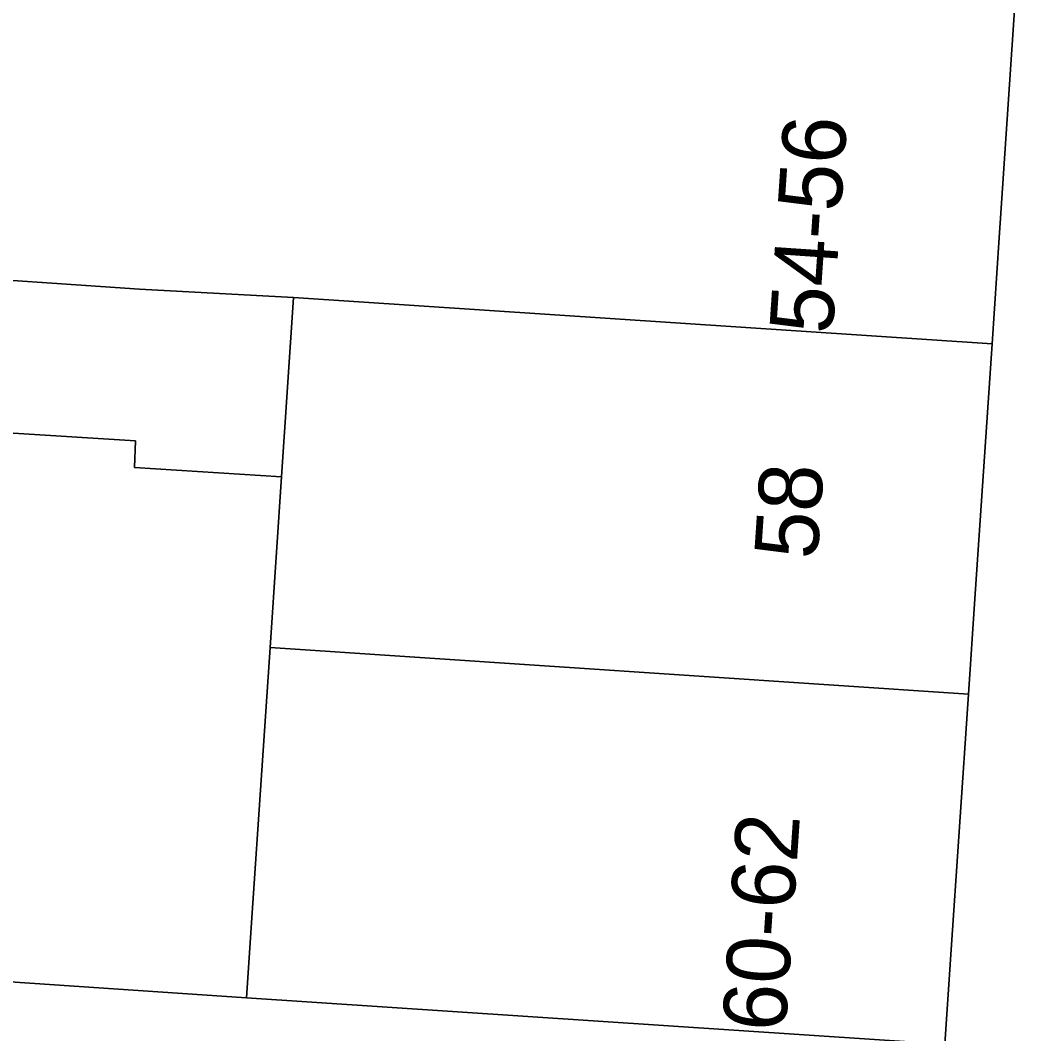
# Model space of a CAD drawing. Extents: x 159960 to 160866, y 382700 to 383354.
# Drawn here: x 160554.15 to 160570.09, y 382879.56 to 382895.53 of the extents above; entities that cross this region are included whole.
import ezdxf

# ---------------------------------------------------------------- set-up
doc = ezdxf.new("R2010")
doc.units = 0
for name, color, linetype in [('IMGEO_Erf', 7, 'Continuous'), ('IMGEO_Pand', 7, 'Continuous'), ('IMGEO_Pand_nummerreeks', 7, 'Continuous'), ('IMGEO_Voetpad_open', 7, 'Continuous')]:
    doc.layers.add(name, color=color, linetype=linetype)

msp = doc.modelspace()

# ---------------------------------------------------------------- linework, layer by layer
at = {"layer": 'IMGEO_Erf'}
msp.add_lwpolyline([(160558.093, 382885.645), (160558.195, 382887.149), (160558.275, 382888.339), (160555.958, 382888.484), (160555.97, 382888.904), (160550.348, 382889.255), (160550.318, 382887.835), (160545.028, 382888.202), (160545.001, 382887.778), (160544.75, 382881.002), (160557.721, 382880.127), (160557.811, 382881.464)], close=True, dxfattribs=at)
at = {"layer": 'IMGEO_Pand'}
for points in [[(160569.847, 382895.857), (160558.833, 382896.589), (160552.857, 382896.986), (160552.795, 382896.076), (160552.96, 382896.065), (160552.651, 382891.528), (160556.037, 382891.294), (160558.466, 382891.163), (160569.48, 382890.432), (160569.593, 382892.102)], [(160558.466, 382891.163), (160556.037, 382891.294), (160552.651, 382891.528), (160547.258, 382891.902), (160545.277, 382892.039), (160545.028, 382888.202), (160550.318, 382887.835), (160550.348, 382889.255), (160555.97, 382888.904), (160555.958, 382888.484), (160558.275, 382888.339)], [(160569.48, 382890.432), (160558.466, 382891.163), (160558.275, 382888.339), (160558.195, 382887.149), (160558.093, 382885.645), (160569.108, 382884.914), (160569.209, 382886.416)], [(160557.721, 382880.127), (160568.735, 382879.396), (160568.825, 382880.731), (160569.108, 382884.914), (160558.093, 382885.645), (160557.811, 382881.464)], [(160557.348, 382874.613), (160568.361, 382873.881), (160568.44, 382875.045), (160568.735, 382879.396), (160557.721, 382880.127), (160544.75, 382881.002), (160544.567, 382878.278), (160547.557, 382877.585), (160547.49, 382876.598), (160557.549, 382877.583)]]:
    msp.add_lwpolyline(points, close=True, dxfattribs=at)
at = {"layer": 'IMGEO_Voetpad_open'}
msp.add_lwpolyline([(160571.511, 382912.196), (160571.174, 382907.212), (160570.918, 382903.429), (160570.361, 382903.466), (160570.263, 382902.012), (160570.214, 382901.282), (160569.977, 382897.787), (160569.847, 382895.857), (160569.593, 382892.102), (160569.48, 382890.432), (160569.209, 382886.416), (160569.108, 382884.914), (160568.825, 382880.731), (160568.735, 382879.396)], dxfattribs=at)

# ---------------------------------------------------------------- texts
at = {"layer": 'IMGEO_Pand_nummerreeks'}
for s, rotation, p in [('54-56', 86.1327, (160566.964, 382890.575)), ('58', 86.1327, (160566.725, 382887.024)), ('60-62', 86.1349, (160566.221, 382879.579))]:
    msp.add_text(s, height=1, rotation=rotation, dxfattribs=at).set_placement(p)

doc.saveas('drawing.dxf')
